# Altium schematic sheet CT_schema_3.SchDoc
size 212 x 173 mm
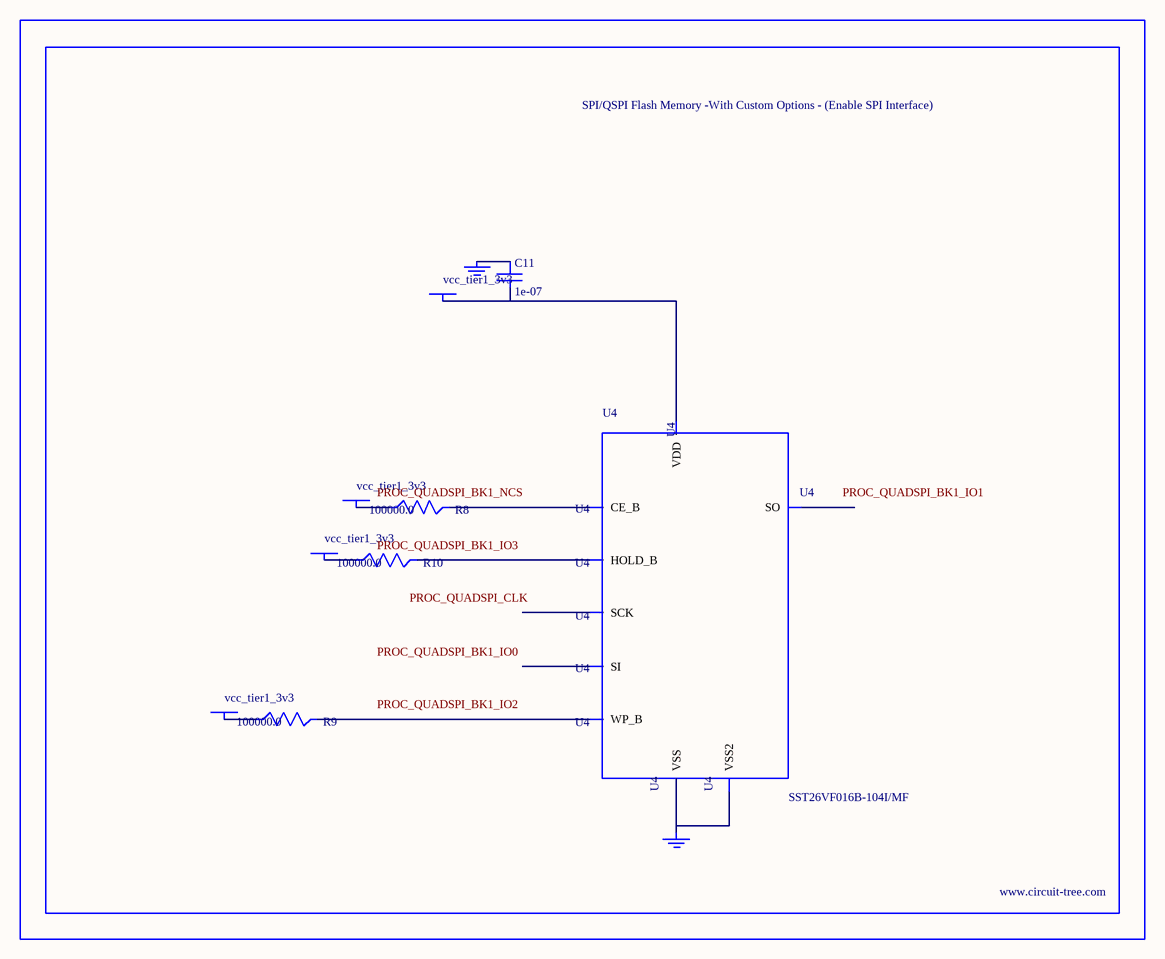
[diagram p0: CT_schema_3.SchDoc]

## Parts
BORDER2  (no value)
C11  1e-07  [C0402]
GND_INSTANCE_2_0  (no value)
GND_INSTANCE_2_1  (no value)
POWER_INSTANCE_2_0  vcc_tier1_3v3
POWER_INSTANCE_2_1  vcc_tier1_3v3
POWER_INSTANCE_2_2  vcc_tier1_3v3
POWER_INSTANCE_2_3  vcc_tier1_3v3
R8  100000.0  [R0603]
R9  100000.0  [R0603]
R10  100000.0  [R0603]
U4  SST26VF016B-104I/MF  [WFDN-8]

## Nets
NetC11_1: C11.1 GND_INSTANCE_2_0.0(GND)
NetC11_2: C11.2 POWER_INSTANCE_2_3.0(PWR) U4.8(VDD)
NetGND_INSTANCE_2_1_0: GND_INSTANCE_2_1.0(GND) U4.4(VSS) U4.9(VSS2)
NetPOWER_INSTANCE_2_0_0: POWER_INSTANCE_2_0.0(PWR) R8.1
NetPOWER_INSTANCE_2_1_0: POWER_INSTANCE_2_1.0(PWR) R9.1
NetPOWER_INSTANCE_2_2_0: POWER_INSTANCE_2_2.0(PWR) R10.1
NetR8_2: R8.2 U4.1(CE_B)
NetR9_2: R9.2 U4.3(WP_B)
NetR10_2: R10.2 U4.7(HOLD_B)

Not connected (* = marked no-connect by the designer): U4 2(SO) 5(SI) 6(SCK)

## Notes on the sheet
- Labels drawn without touching a wire or pin: PROC_QUADSPI_BK1_IO0, PROC_QUADSPI_BK1_IO1, PROC_QUADSPI_BK1_IO2, PROC_QUADSPI_BK1_IO3, PROC_QUADSPI_BK1_NCS, PROC_QUADSPI_CLK

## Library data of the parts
BORDER2 = BORDER_PAGE2
C11 = C0402C104K3RACTU
GND_INSTANCE_2_0 GND_INSTANCE_2_1 = GND
POWER_INSTANCE_2_0-POWER_INSTANCE_2_3 = PWR
R8-R10 = RC0603JR-07100KL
